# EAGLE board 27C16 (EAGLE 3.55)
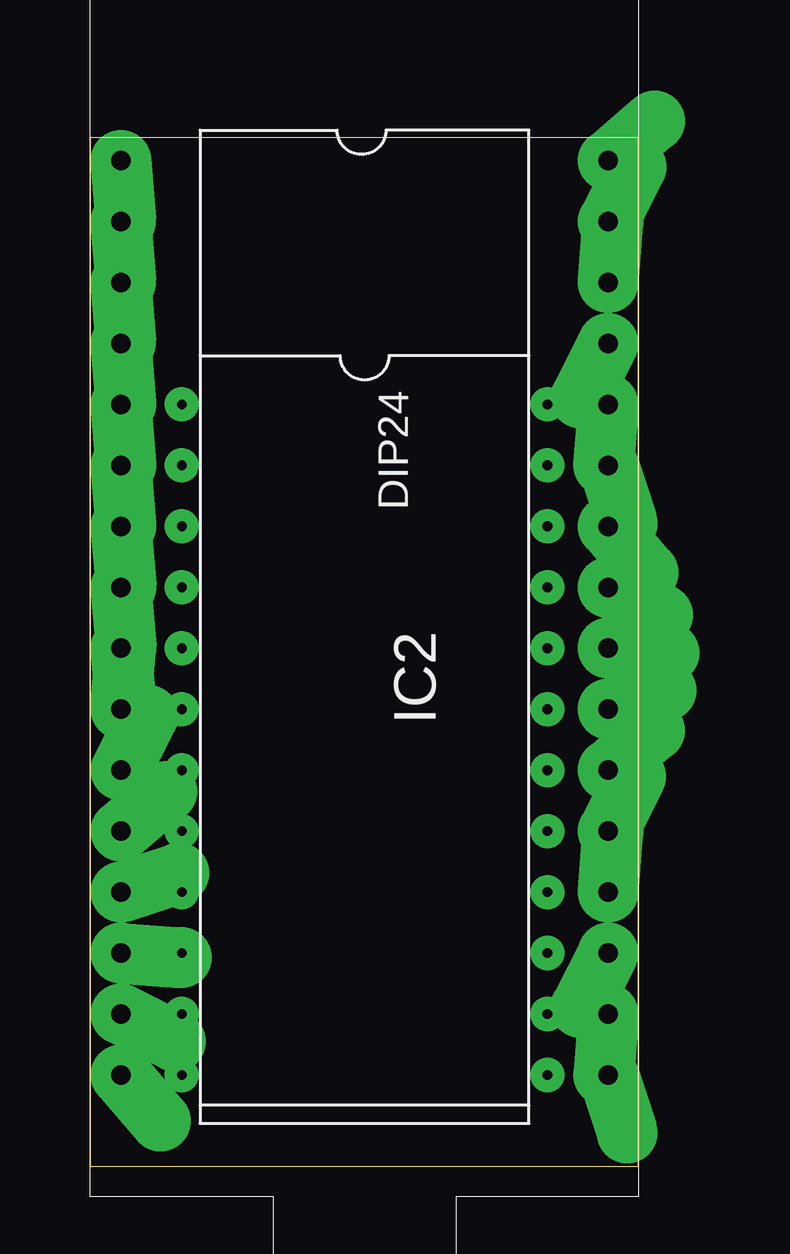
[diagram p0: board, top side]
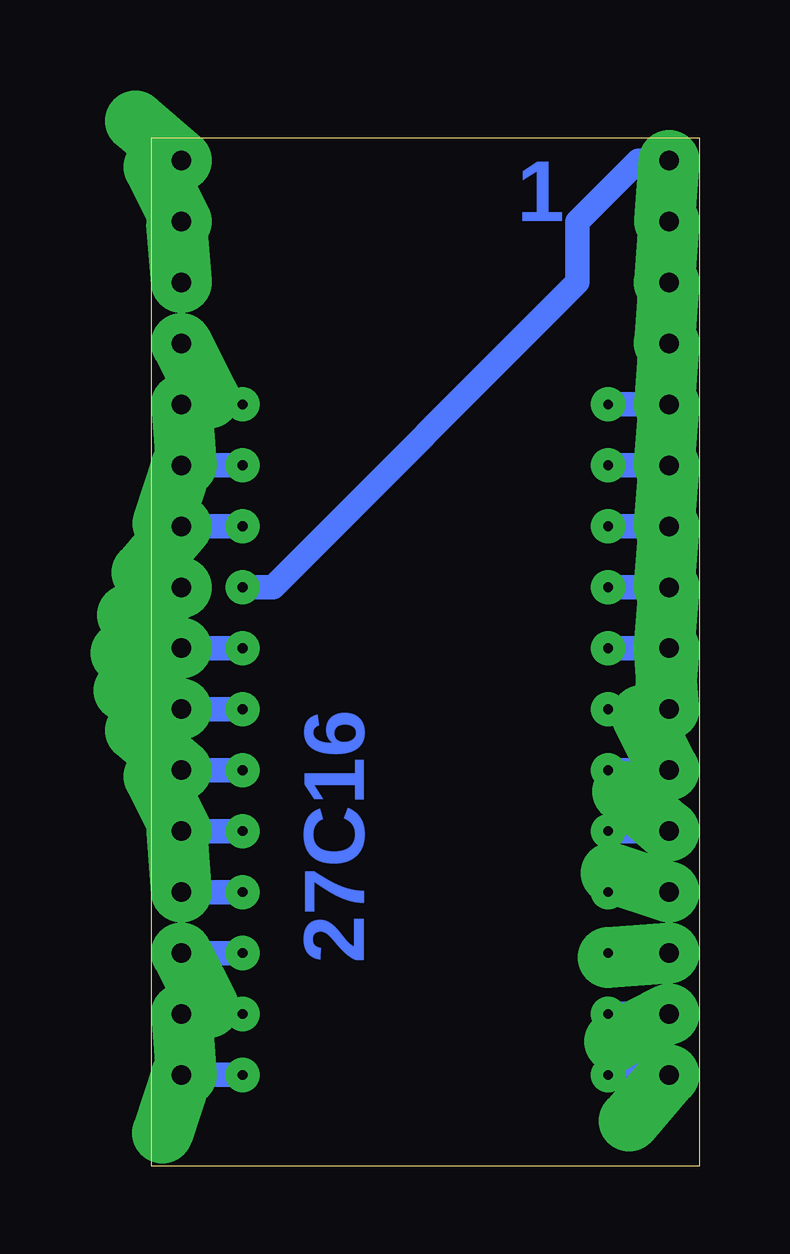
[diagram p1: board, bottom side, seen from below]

Size 22.84 x 42.85 mm. Coordinates in mm from the lower left corner, seen from the top.
Outline: 0,0 22.84,0 22.84,42.85 0,42.85 0,0
Copper layers used: Bottom

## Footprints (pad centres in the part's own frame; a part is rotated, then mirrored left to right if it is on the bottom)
L-24 = drill 0.406 pad 1.422 round:  0,0;  2.54,0;  5.08,0;  7.62,0;  10.16,0;  12.7,0;  15.24,0;  17.78,0;  20.32,0;  22.86,0;  25.4,0;  27.94,0;  27.94,15.24;  25.4,15.24;  22.86,15.24;  20.32,15.24;  17.78,15.24;  15.24,15.24;  12.7,15.24;  10.16,15.24;  7.62,15.24;  5.08,15.24;  2.54,15.24;  0,15.24
AOV32 = drill 0.813 pad 2.54 offset:  -19.05,-10.16;  -16.51,-10.16;  -3.81,-10.16;  -1.27,-10.16;  -13.97,-10.16;  -11.43,-10.16;  -6.35,-10.16;  -8.89,-10.16;  1.27,-10.16;  3.81,-10.16;  6.35,-10.16;  8.89,-10.16;  11.43,-10.16;  13.97,-10.16;  16.51,-10.16;  19.05,-10.16;  19.05,10.16;  16.51,10.16;  13.97,10.16;  11.43,10.16;  8.89,10.16;  6.35,10.16;  3.81,10.16;  1.27,10.16;  -1.27,10.16;  -3.81,10.16;  -6.35,10.16;  -8.89,10.16;  -11.43,10.16;  -13.97,10.16;  -16.51,10.16;  -19.05,10.16

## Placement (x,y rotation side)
DIP24  [L-24]  3.81,31.75 270 top
IC2  TEXTOEP_32  [AOV32]  11.43,22.86 270 top

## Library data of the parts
DIP24 = holg_plt
IC2 = galeprom

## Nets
+5V: IC2.
GND: DIP24. IC2.
S$1: DIP24. IC2.
S$2: DIP24. IC2.
S$3: DIP24. IC2.
S$4: DIP24. IC2.
S$5: DIP24. IC2.
S$6: DIP24. IC2.
S$7: DIP24. IC2.
S$8: DIP24. IC2.
S$9: DIP24. IC2.
S$10: DIP24. IC2.
S$11: DIP24. IC2.
S$12: DIP24. IC2.
S$13: DIP24. IC2.
S$14: DIP24. IC2.
S$15: DIP24. IC2.
S$16: DIP24. IC2.
S$17: DIP24. IC2.
S$18: DIP24. IC2.
S$19: DIP24. IC2.
S$20: DIP24. IC2.
S$21: DIP24. IC2.
S$22: DIP24. IC2.
S$23: DIP24. IC2.

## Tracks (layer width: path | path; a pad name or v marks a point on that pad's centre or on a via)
GND
  Bottom 1.016: 1.27,3.81 3.81,3.81
S$1
  Bottom 1.016: 1.27,31.75 3.81,31.75
S$2
  Bottom 1.016: 1.27,29.21 3.81,29.21
S$3
  Bottom 1.016: 1.27,26.67 3.81,26.67
S$4
  Bottom 1.016: 1.27,24.13 3.81,24.13
S$5
  Bottom 1.016: 1.27,21.59 3.81,21.59
S$6
  Bottom 1.016: 1.27,19.05 3.81,19.05
S$7
  Bottom 1.016: 1.27,16.51 3.81,16.51
S$8
  Bottom 1.016: 1.27,13.97 3.81,13.97
S$9
  Bottom 1.016: 1.27,11.43 3.81,11.43
S$10
  Bottom 1.016: 1.27,8.89 3.81,8.89
S$11
  Bottom 1.016: 1.27,6.35 3.81,6.35
S$12
  Bottom 1.016: DIP24. 21.59,31.75
S$13
  Bottom 1.016: 19.05,3.81 21.59,3.81
S$14
  Bottom 1.016: 19.05,6.35 21.59,6.35
S$15
  Bottom 1.016: 19.05,8.89 21.59,8.89
S$16
  Bottom 1.016: 19.05,11.43 21.59,11.43
S$17
  Bottom 1.016: 19.05,13.97 21.59,13.97
S$18
  Bottom 1.016: 19.05,29.21 21.59,29.21
S$19
  Bottom 1.016: 19.05,26.67 21.59,26.67
S$20
  Bottom 1.016: 19.05,21.59 21.59,21.59
S$21
  Bottom 1.016: 19.05,19.05 21.59,19.05
S$22
  Bottom 1.016: 19.05,16.51 21.59,16.51
S$23
  Bottom 1.016: 19.05,24.13 17.78,24.13 5.08,36.83 5.08,39.37 2.54,41.91 1.27,41.91

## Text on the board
Bottom: 1 | 27C16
